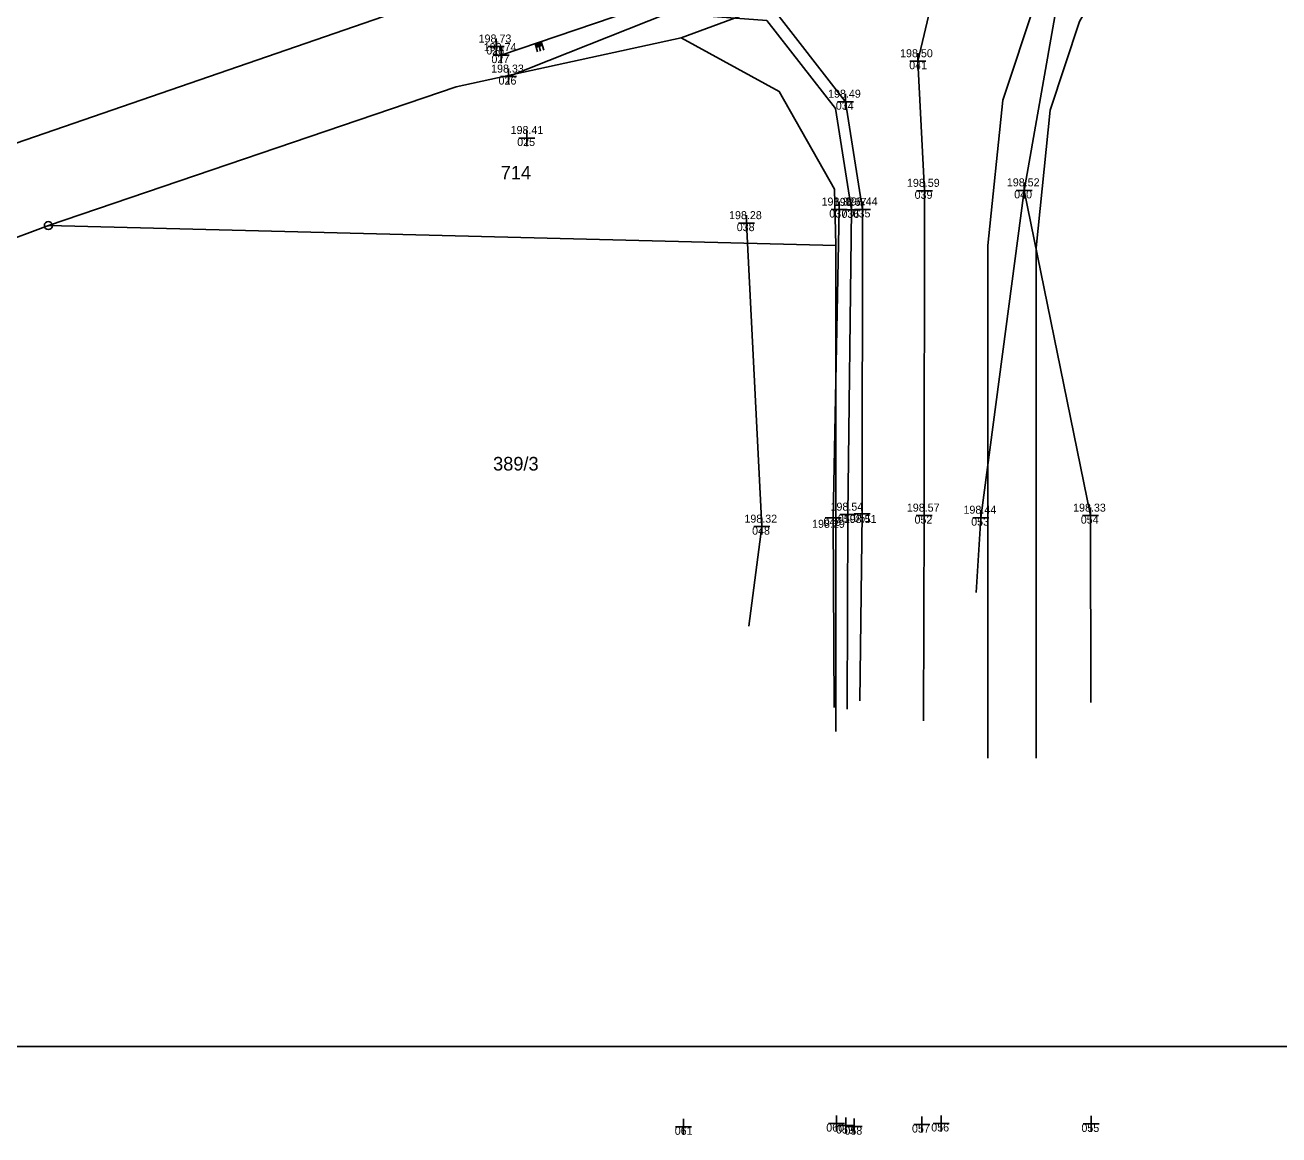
# Model space of a CAD drawing. Extents: x -706655 to -706193, y -1036183 to -1035040.
# Drawn here: x -706461.2 to -706382.9, y -1035290.9 to -1035221.5 of the extents above; entities that cross this region are included whole.
import ezdxf

# ---------------------------------------------------------------- set-up
doc = ezdxf.new("R2010")
doc.units = 0
for name, color, linetype in [('Hranice parcel', 7, 'Continuous'), ('křížky', 7, 'Continuous'), ('Parcelní čísla', 7, 'Continuous'), ('Stávající terén', 7, 'Continuous'), ('Vrstva 54', 7, 'Continuous'), ('výšky', 7, 'Continuous'), ('Značky bodu BP', 7, 'Continuous'), ('čísla bodu', 7, 'Continuous')]:
    doc.layers.add(name, color=color, linetype=linetype)

msp = doc.modelspace()

# ---------------------------------------------------------------- linework, layer by layer
at = {"layer": 'Hranice parcel'}
for p, q in [((-706420.22, -1035222.31), (-706388.41, -1035210.6)), ((-706477.77, -1035234.42), (-706432.87, -1035218.92)), ((-706459.76, -1035234.05), (-706477.588, -1035240.664)), ((-706410.54, -1035235.29), (-706459.76, -1035234.05)), ((-706410.54, -1035265.68), (-706410.54, -1035235.29))]:
    msp.add_line(p, q, dxfattribs=at)
for points in [[(-706401.04, -1035267.33), (-706401.04, -1035235.29), (-706400.11, -1035226.21), (-706398.07, -1035220.07), (-706394.74, -1035214.25), (-706388.41, -1035210.6)], [(-706398.04, -1035267.33), (-706398.04, -1035235.44), (-706397.16, -1035226.84), (-706395.32, -1035221.3), (-706392.54, -1035216.45), (-706387.38, -1035213.42)], [(-706459.76, -1035234.05), (-706434.28, -1035225.37), (-706420.22, -1035222.31)], [(-706410.54, -1035235.29), (-706410.64, -1035231.77), (-706414.08, -1035225.67), (-706420.22, -1035222.31)]]:
    msp.add_lwpolyline(points, dxfattribs=at)
at = {"layer": 'křížky'}
for p, q in [((-706431.78, -1035223.36), (-706431.78, -1035222.36)), ((-706432.28, -1035222.86), (-706431.28, -1035222.86)), ((-706431.78, -1035222.86), (-706431.78, -1035222.86)), ((-706431.46, -1035223.9), (-706431.46, -1035222.9)), ((-706431.96, -1035223.4), (-706430.96, -1035223.4)), ((-706431.46, -1035223.4), (-706431.46, -1035223.4)), ((-706405.92, -1035223.78), (-706404.92, -1035223.78)), ((-706405.42, -1035224.28), (-706405.42, -1035223.28)), ((-706405.42, -1035223.78), (-706405.42, -1035223.78)), ((-706431, -1035225.24), (-706431, -1035224.24)), ((-706431.5, -1035224.74), (-706430.5, -1035224.74)), ((-706431, -1035224.74), (-706431, -1035224.74)), ((-706409.94, -1035226.81), (-706409.94, -1035225.81)), ((-706410.44, -1035226.31), (-706409.44, -1035226.31)), ((-706409.94, -1035226.31), (-706409.94, -1035226.31)), ((-706430.35, -1035228.58), (-706429.35, -1035228.58)), ((-706429.85, -1035229.08), (-706429.85, -1035228.08)), ((-706429.85, -1035228.58), (-706429.85, -1035228.58)), ((-706405.01, -1035232.38), (-706405.01, -1035231.38)), ((-706398.77, -1035232.35), (-706398.77, -1035231.35)), ((-706410.35, -1035233.55), (-706410.35, -1035232.55)), ((-706408.89, -1035233.54), (-706408.89, -1035232.54)), ((-706405.51, -1035231.88), (-706404.51, -1035231.88)), ((-706405.01, -1035231.88), (-706405.01, -1035231.88)), ((-706399.27, -1035231.85), (-706398.27, -1035231.85)), ((-706398.77, -1035231.85), (-706398.77, -1035231.85)), ((-706410.85, -1035233.05), (-706409.85, -1035233.05)), ((-706410.35, -1035233.05), (-706410.35, -1035233.05)), ((-706410.07, -1035233.07), (-706409.07, -1035233.07)), ((-706409.57, -1035233.57), (-706409.57, -1035232.57)), ((-706409.57, -1035233.07), (-706409.57, -1035233.07)), ((-706409.39, -1035233.04), (-706408.39, -1035233.04)), ((-706408.89, -1035233.04), (-706408.89, -1035233.04)), ((-706416.63, -1035233.9), (-706415.63, -1035233.9)), ((-706416.13, -1035234.4), (-706416.13, -1035233.4)), ((-706416.13, -1035233.9), (-706416.13, -1035233.9)), ((-706410.71, -1035252.82), (-706410.71, -1035251.82)), ((-706410.29, -1035252.12), (-706409.29, -1035252.12)), ((-706409.79, -1035252.62), (-706409.79, -1035251.62)), ((-706409.79, -1035252.12), (-706409.79, -1035252.12)), ((-706409.41, -1035252.07), (-706408.41, -1035252.07)), ((-706408.91, -1035252.57), (-706408.91, -1035251.57)), ((-706408.91, -1035252.07), (-706408.91, -1035252.07)), ((-706405.02, -1035252.68), (-706405.02, -1035251.68)), ((-706401.48, -1035252.81), (-706401.48, -1035251.81)), ((-706394.63, -1035252.68), (-706394.63, -1035251.68)), ((-706415.67, -1035252.87), (-706414.67, -1035252.87)), ((-706415.17, -1035253.37), (-706415.17, -1035252.37)), ((-706415.17, -1035252.87), (-706415.17, -1035252.87)), ((-706411.21, -1035252.32), (-706410.21, -1035252.32)), ((-706410.71, -1035252.32), (-706410.71, -1035252.32)), ((-706405.52, -1035252.18), (-706404.52, -1035252.18)), ((-706405.02, -1035252.18), (-706405.02, -1035252.18)), ((-706401.98, -1035252.31), (-706400.98, -1035252.31)), ((-706401.48, -1035252.31), (-706401.48, -1035252.31)), ((-706395.13, -1035252.18), (-706394.13, -1035252.18)), ((-706394.63, -1035252.18), (-706394.63, -1035252.18))]:
    msp.add_line(p, q, dxfattribs=at)
at = {"layer": 'Stávající terén'}
for p, q in [((-706429.347, -1035222.679), (-706429.186, -1035223.201)), ((-706429.252, -1035222.645), (-706429.166, -1035222.927)), ((-706429.158, -1035222.612), (-706428.995, -1035223.142)), ((-706429.064, -1035222.578), (-706428.975, -1035222.868)), ((-706428.97, -1035222.544), (-706428.804, -1035223.084)), ((-706401.48, -1035252.31), (-706398.77, -1035231.85)), ((-706394.63, -1035252.18), (-706398.77, -1035231.85))]:
    msp.add_line(p, q, dxfattribs=at)
for points in [[(-706394.17, -1035209.4), (-706400.57, -1035213.32), (-706404.16, -1035218.4), (-706405.42, -1035223.78), (-706405.01, -1035231.88), (-706405.02, -1035252.18), (-706405.074, -1035265.009)], [(-706398.77, -1035231.85), (-706396.81, -1035220.63), (-706395.67, -1035216.55), (-706391.1, -1035214.26)], [(-706431.46, -1035223.4), (-706420.96, -1035219.82), (-706414.52, -1035220.43), (-706409.94, -1035226.31), (-706408.89, -1035233.04), (-706408.91, -1035252.07), (-706409.059, -1035263.746)], [(-706409.831, -1035264.273), (-706409.79, -1035252.12), (-706409.57, -1035233.07), (-706410.57, -1035226.73), (-706414.87, -1035221.23), (-706421.03, -1035220.77), (-706431, -1035224.74)], [(-706410.35, -1035233.05), (-706410.71, -1035252.32), (-706410.644, -1035264.17)], [(-706416.13, -1035233.9), (-706415.17, -1035252.87), (-706415.98, -1035259.084)], [(-706401.48, -1035252.31), (-706401.786, -1035256.982)], [(-706394.618, -1035263.861), (-706394.63, -1035252.18)]]:
    msp.add_lwpolyline(points, dxfattribs=at)
at = {"layer": 'Vrstva 54'}
msp.add_lwpolyline([(-706654.6, -1035040.151), (-706286.789, -1035040.151), (-706286.789, -1035285.37), (-706654.6, -1035285.37)], close=True, dxfattribs=at)
at = {"layer": 'Značky bodu BP'}
for radius in [0.25, 0.0152]:
    msp.add_circle((-706459.76, -1035234.05), radius, dxfattribs=at)
at = {"layer": 'čísla bodu'}
for p, q in [((-706431.78, -1035223.36), (-706431.78, -1035222.36)), ((-706432.28, -1035222.86), (-706431.28, -1035222.86)), ((-706431.78, -1035222.86), (-706431.78, -1035222.86)), ((-706431.46, -1035223.9), (-706431.46, -1035222.9)), ((-706431.96, -1035223.4), (-706430.96, -1035223.4)), ((-706431.46, -1035223.4), (-706431.46, -1035223.4)), ((-706405.92, -1035223.78), (-706404.92, -1035223.78)), ((-706405.42, -1035224.28), (-706405.42, -1035223.28)), ((-706405.42, -1035223.78), (-706405.42, -1035223.78)), ((-706431, -1035225.24), (-706431, -1035224.24)), ((-706431.5, -1035224.74), (-706430.5, -1035224.74)), ((-706431, -1035224.74), (-706431, -1035224.74)), ((-706409.94, -1035226.81), (-706409.94, -1035225.81)), ((-706410.44, -1035226.31), (-706409.44, -1035226.31)), ((-706409.94, -1035226.31), (-706409.94, -1035226.31)), ((-706430.35, -1035228.58), (-706429.35, -1035228.58)), ((-706429.85, -1035229.08), (-706429.85, -1035228.08)), ((-706429.85, -1035228.58), (-706429.85, -1035228.58)), ((-706405.01, -1035232.38), (-706405.01, -1035231.38)), ((-706398.77, -1035232.35), (-706398.77, -1035231.35)), ((-706410.35, -1035233.55), (-706410.35, -1035232.55)), ((-706408.89, -1035233.54), (-706408.89, -1035232.54)), ((-706405.51, -1035231.88), (-706404.51, -1035231.88)), ((-706405.01, -1035231.88), (-706405.01, -1035231.88)), ((-706399.27, -1035231.85), (-706398.27, -1035231.85)), ((-706398.77, -1035231.85), (-706398.77, -1035231.85)), ((-706410.85, -1035233.05), (-706409.85, -1035233.05)), ((-706410.35, -1035233.05), (-706410.35, -1035233.05)), ((-706410.07, -1035233.07), (-706409.07, -1035233.07)), ((-706409.57, -1035233.57), (-706409.57, -1035232.57)), ((-706409.57, -1035233.07), (-706409.57, -1035233.07)), ((-706409.39, -1035233.04), (-706408.39, -1035233.04)), ((-706408.89, -1035233.04), (-706408.89, -1035233.04)), ((-706416.63, -1035233.9), (-706415.63, -1035233.9)), ((-706416.13, -1035234.4), (-706416.13, -1035233.4)), ((-706416.13, -1035233.9), (-706416.13, -1035233.9)), ((-706410.71, -1035252.82), (-706410.71, -1035251.82)), ((-706410.29, -1035252.12), (-706409.29, -1035252.12)), ((-706409.79, -1035252.62), (-706409.79, -1035251.62)), ((-706409.79, -1035252.12), (-706409.79, -1035252.12)), ((-706409.41, -1035252.07), (-706408.41, -1035252.07)), ((-706408.91, -1035252.57), (-706408.91, -1035251.57)), ((-706408.91, -1035252.07), (-706408.91, -1035252.07)), ((-706405.02, -1035252.68), (-706405.02, -1035251.68)), ((-706401.48, -1035252.81), (-706401.48, -1035251.81)), ((-706394.63, -1035252.68), (-706394.63, -1035251.68)), ((-706415.67, -1035252.87), (-706414.67, -1035252.87)), ((-706415.17, -1035253.37), (-706415.17, -1035252.37)), ((-706415.17, -1035252.87), (-706415.17, -1035252.87)), ((-706411.21, -1035252.32), (-706410.21, -1035252.32)), ((-706410.71, -1035252.32), (-706410.71, -1035252.32)), ((-706405.52, -1035252.18), (-706404.52, -1035252.18)), ((-706405.02, -1035252.18), (-706405.02, -1035252.18)), ((-706401.98, -1035252.31), (-706400.98, -1035252.31)), ((-706401.48, -1035252.31), (-706401.48, -1035252.31)), ((-706395.13, -1035252.18), (-706394.13, -1035252.18)), ((-706394.63, -1035252.18), (-706394.63, -1035252.18)), ((-706410.5, -1035290.68), (-706410.5, -1035289.68)), ((-706405.18, -1035290.74), (-706405.18, -1035289.74)), ((-706403.96, -1035290.67), (-706403.96, -1035289.67)), ((-706394.59, -1035290.7), (-706394.59, -1035289.7)), ((-706420.56, -1035290.38), (-706419.56, -1035290.38)), ((-706420.06, -1035290.88), (-706420.06, -1035289.88)), ((-706420.06, -1035290.38), (-706420.06, -1035290.38)), ((-706411, -1035290.18), (-706410, -1035290.18)), ((-706410.5, -1035290.18), (-706410.5, -1035290.18)), ((-706410.42, -1035290.3), (-706409.42, -1035290.3)), ((-706409.92, -1035290.8), (-706409.92, -1035289.8)), ((-706409.92, -1035290.3), (-706409.92, -1035290.3)), ((-706409.9, -1035290.37), (-706408.9, -1035290.37)), ((-706409.4, -1035290.87), (-706409.4, -1035289.87)), ((-706409.4, -1035290.37), (-706409.4, -1035290.37)), ((-706405.68, -1035290.24), (-706404.68, -1035290.24)), ((-706405.18, -1035290.24), (-706405.18, -1035290.24)), ((-706404.46, -1035290.17), (-706403.46, -1035290.17)), ((-706403.96, -1035290.17), (-706403.96, -1035290.17)), ((-706395.09, -1035290.2), (-706394.09, -1035290.2)), ((-706394.59, -1035290.2), (-706394.59, -1035290.2))]:
    msp.add_line(p, q, dxfattribs=at)

# ---------------------------------------------------------------- texts
at = {"layer": 'Parcelní čísla'}
for s, p in [('714', (-706431.492, -1035231.169)), ('389/3', (-706431.967, -1035249.36))]:
    msp.add_text(s, height=0.85, dxfattribs=at).set_placement(p)
at = {"layer": 'výšky'}
for s, p in [('198.73', (-706432.872, -1035222.61)), ('198.74', (-706432.552, -1035223.15)), ('198.50', (-706406.534, -1035223.53)), ('198.33', (-706432.092, -1035224.49)), ('198.49', (-706411.034, -1035226.06)), ('198.41', (-706430.873, -1035228.33)), ('198.59', (-706406.104, -1035231.63)), ('198.52', (-706399.862, -1035231.6)), ('198.32', (-706411.442, -1035232.8)), ('198.67', (-706410.676, -1035232.82)), ('198.44', (-706409.982, -1035232.79)), ('198.28', (-706417.222, -1035233.65)), ('198.54', (-706410.882, -1035251.87)), ('198.32', (-706416.262, -1035252.62)), ('198.51', (-706410.053, -1035252.64)), ('198.57', (-706406.112, -1035251.93)), ('198.44', (-706402.572, -1035252.06)), ('198.33', (-706395.722, -1035251.93)), ('198.29', (-706412.034, -1035252.94))]:
    msp.add_text(s, height=0.5, dxfattribs=at).set_placement(p)
at = {"layer": 'čísla bodu'}
for s, p in [('028', (-706432.392, -1035223.36)), ('027', (-706432.072, -1035223.9)), ('041', (-706405.962, -1035224.28)), ('026', (-706431.626, -1035225.24)), ('034', (-706410.552, -1035226.81)), ('025', (-706430.462, -1035229.08)), ('039', (-706405.624, -1035232.38)), ('040', (-706399.404, -1035232.35)), ('037', (-706410.962, -1035233.55)), ('036', (-706410.196, -1035233.57)), ('035', (-706409.502, -1035233.54)), ('038', (-706416.742, -1035234.4)), ('050', (-706410.424, -1035252.62)), ('051', (-706409.452, -1035252.57)), ('048', (-706415.782, -1035253.37)), ('049', (-706411.324, -1035252.82)), ('052', (-706405.632, -1035252.68)), ('053', (-706402.092, -1035252.81)), ('054', (-706395.242, -1035252.68)), ('061', (-706420.616, -1035290.88)), ('060', (-706411.147, -1035290.68)), ('059', (-706410.534, -1035290.8)), ('058', (-706410.012, -1035290.87)), ('057', (-706405.792, -1035290.74)), ('056', (-706404.586, -1035290.67)), ('055', (-706395.202, -1035290.7))]:
    msp.add_text(s, height=0.5, dxfattribs=at).set_placement(p)

doc.saveas('drawing.dxf')
